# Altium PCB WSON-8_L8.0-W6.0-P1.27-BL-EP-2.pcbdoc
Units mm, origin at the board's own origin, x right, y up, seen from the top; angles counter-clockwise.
Board outline 18.76 x 21.95 mm, 2 copper layers (Top Layer, Bottom Layer), stack 0 mm thick; 1 components, 0 nets, 9 pads, 0 vias.
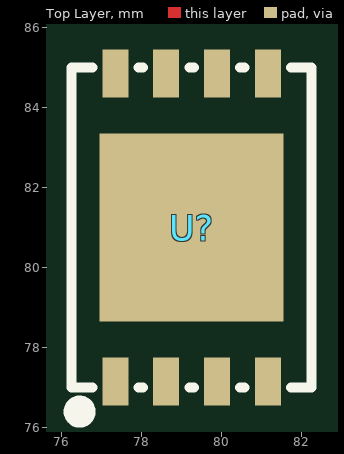
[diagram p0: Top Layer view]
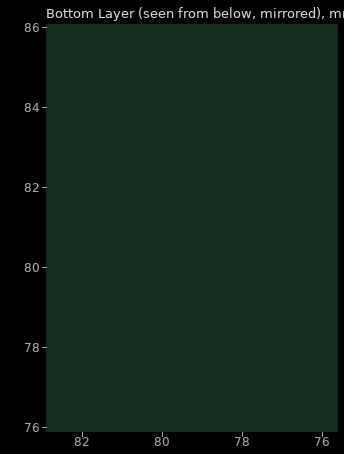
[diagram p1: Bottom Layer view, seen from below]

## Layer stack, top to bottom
Top Layer: signal copper (thickness not stored)
Bottom Layer: signal copper (thickness not stored)

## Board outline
88.61,69.85 69.85,69.85 69.85,91.799 88.61,91.799

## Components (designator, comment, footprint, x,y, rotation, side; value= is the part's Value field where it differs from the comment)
U? "" WSON-8_L8.0-W6.0-P1.27-BL-EP-2 79.26,80.999 r0 top

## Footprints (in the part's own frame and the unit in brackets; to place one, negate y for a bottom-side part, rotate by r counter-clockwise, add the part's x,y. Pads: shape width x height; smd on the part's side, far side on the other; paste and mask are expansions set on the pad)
WSON-8_L8.0-W6.0-P1.27-BL-EP-2 [mm]
  rect 0.65x1.2 smd paste+0 mask+0.05: 1(-1.905,-3.85) 2(-0.635,-3.85) 3(0.635,-3.85) 4(1.905,-3.85) 5(1.905,3.85) 6(0.635,3.85) 7(-0.635,3.85) 8(-1.905,3.85)
  rect 4.6x4.7 smd paste+0 mask+0.05: 9(0,0)
  silkscreen extent -3,-4.8 3,4

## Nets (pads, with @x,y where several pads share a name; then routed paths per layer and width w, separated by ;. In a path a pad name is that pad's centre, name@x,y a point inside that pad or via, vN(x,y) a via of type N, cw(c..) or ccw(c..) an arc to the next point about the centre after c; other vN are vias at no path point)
pads on no net: U?.1 U?.2 U?.3 U?.4 U?.5 U?.6 U?.7 U?.8 U?.9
